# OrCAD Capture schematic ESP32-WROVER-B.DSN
size C; title: ESP32-WROVER-B; rev: 1.0
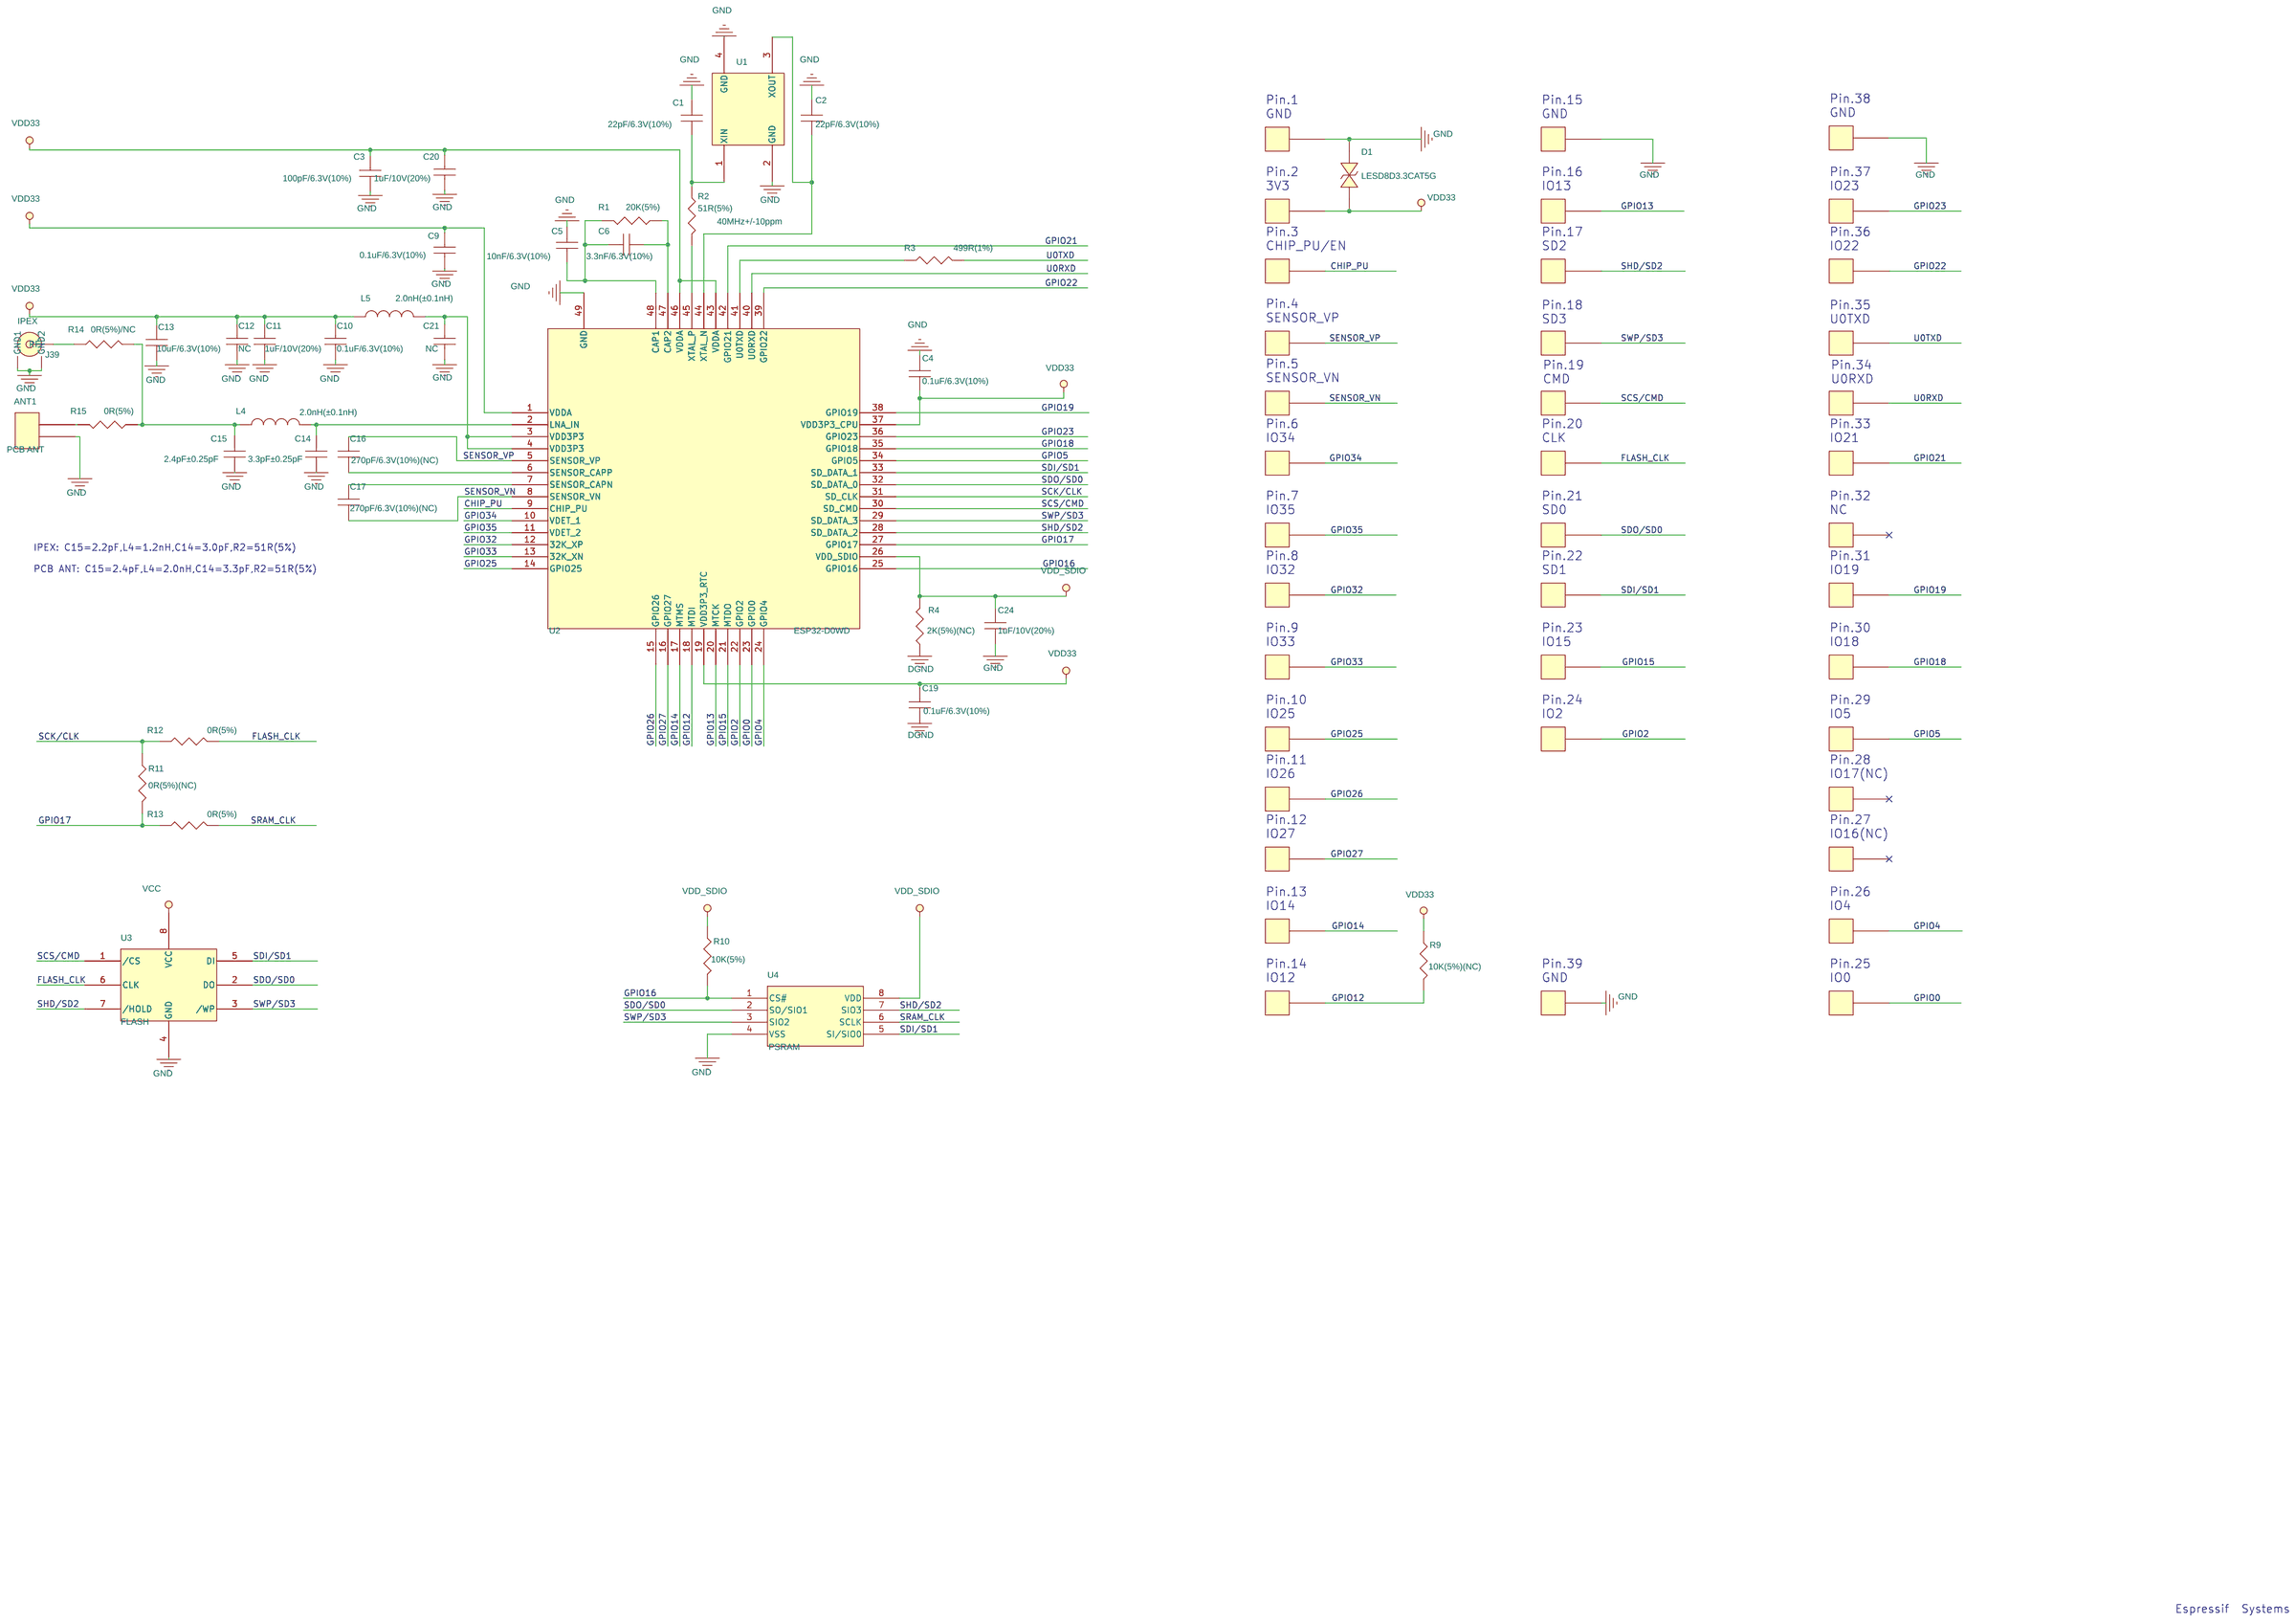
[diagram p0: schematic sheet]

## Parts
ANT1  PCB ANT  [MINI_ANT_TYPEA]
C1  22pF/6.3V(10%)  [C0201]
C2  22pF/6.3V(10%)  [C0201]
C3  100pF/6.3V(10%)  [C0201]
C4  0.1uF/6.3V(10%)  [C0201]
C5  10nF/6.3V(10%)  [C0201]
C6  3.3nF/6.3V(10%)  [C0201]
C9  0.1uF/6.3V(10%)  [C0201]
C10  0.1uF/6.3V(10%)  [C0201]
C11  1uF/10V(20%)  [C0201]
C12  NC  [C0402]
C13  10uF/6.3V(10%)  [C0402]
C14  3.3pF±0.25pF  [C0201]
C15  2.4pF±0.25pF  [C0201]
C16  270pF/6.3V(10%)(NC)  [C0201]
C17  270pF/6.3V(10%)(NC)  [C0201]
C19  0.1uF/6.3V(10%)  [C0201]
C20  1uF/10V(20%)  [C0201]
C21  NC  [C0201]
C24  1uF/10V(20%)  [C0201]
D1  LESD8D3.3CAT5G  [SOD882]
EP  CON1  [SPAD_1]
J1  CON1  [SPAD_1]
J2  CON1  [SPAD_1]
J3  CON1  [SPAD_1]
J4  CON1  [SPAD_1]
J5  CON1  [SPAD_1]
J6  CON1  [SPAD_1]
J7  CON1  [SPAD_1]
J8  CON1  [SPAD_1]
J9  CON1  [SPAD_1]
J10  CON1  [SPAD_1]
J11  CON1  [SPAD_1]
J12  CON1  [SPAD_1]
J13  CON1  [SPAD_1]
J14  CON1  [SPAD_1]
J15  CON1  [SPAD_1]
J16  CON1  [SPAD_1]
J17  CON1  [SPAD_1]
J18  CON1  [SPAD_1]
J19  CON1  [SPAD_1]
J20  CON1  [SPAD_1]
J21  CON1  [SPAD_1]
J22  CON1  [SPAD_1]
J23  CON1  [SPAD_1]
J24  CON1  [SPAD_1]
J25  CON1  [SPAD_1]
J26  CON1  [SPAD_1]
J27  CON1  [SPAD_1]
J28  CON1  [SPAD_1]
J29  CON1  [SPAD_1]
J30  CON1  [SPAD_1]
J31  CON1  [SPAD_1]
J32  CON1  [SPAD_1]
J33  CON1  [SPAD_1]
J34  CON1  [SPAD_1]
J35  CON1  [SPAD_1]
J36  CON1  [SPAD_1]
J37  CON1  [SPAD_1]
J38  CON1  [SPAD_1]
J39  IPEX  [ECT818000368]
L4  2.0nH(±0.1nH)  [L0201]
L5  2.0nH(±0.1nH)  [L0201]
R1  20K(5%)  [R0201]
R2  51R(5%)  [R0201]
R3  499R(1%)  [R0201]
R4  2K(5%)(NC)  [R0201]
R9  10K(5%)(NC)  [R0201]
R10  10K(5%)  [R0201]
R11  0R(5%)(NC)  [R0201]
R12  0R(5%)  [R0201]
R13  0R(5%)  [R0201]
R14  0R(5%)/NC  [R0201A]
R15  0R(5%)  [R0201A]
U1  40MHz+/-10ppm  [3225]
U2  ESP32-D0WD  [SLP48_5X5]
U3  FLASH  [SOIC08-WN]
U4  PSRAM  [SOIC-8P]

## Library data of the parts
ANT1 = CON2
C1-C6 C9-C17 C19-C21 C24 = CAP_NP
D1 = DIODE_BI-DIR_TRIG: Options: ESD
EP J1-J38 = CON1
J39 = IPEX_0
L4 L5 = CHOKE
R1-R4 R9-R15 = RESISTOR
U1 = X1_1
U2 = ESP8080_24
U3 = FLASH_3
U4 = PN18S32

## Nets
GND: ANT1.2 C1.2 C2.2 C3.2 C4.2 C5.2 C9.2 C10.2 C11.2 C12.2 C13.2 C14.1 C15.1 C19.2 C20.2 C21.2 C24.2 D1.2 EP.1 J1.1 J5.1 J28.1 J39.2(GND1) J39.3(GND2) R4.2 U1.2(GND) U1.4(GND) U2.49(GND) U3.4(GND) U4.4(VSS)
VDD33: C3.1 C4.1 C9.1 C10.1 C11.1 C12.1 C13.1 C19.1 C20.1 D1.1 J3.1 L5.2 R9.1 U2.1(VDDA) U2.19(VDD3P3_RTC) U2.37(VDD3P3_CPU) U2.43(VDDA) U2.46(VDDA)
VDD_SDIO: C24.1 R4.1 R10.1 U2.26(VDD_SDIO) U3.8(VCC) U4.8(VDD)
CHIP_PU: J6.1 U2.9(CHIP_PU)
FLASH_CLK: J19.1 R12.2 U3.6(CLK)
GPIO0: J34.1 U2.23(GPIO0)
GPIO2: J36.1 U2.22(GPIO2)
GPIO4: J32.1 U2.24(GPIO4)
GPIO5: J24.1 U2.34(GPIO5)
GPIO12: J35.1 R9.2 U2.18(MTDI)
GPIO13: J37.1 U2.20(MTCK)
GPIO14: J33.1 U2.17(MTMS)
GPIO15: J38.1 U2.21(MTDO)
GPIO16: R10.2 U2.25(GPIO16) U4.1(CS#)
GPIO17: R11.2 R13.1 U2.27(GPIO17)
GPIO18: J21.1 U2.35(GPIO18)
GPIO19: J18.1 U2.38(GPIO19)
GPIO21: J12.1 U2.42(GPIO21)
GPIO22: J4.1 U2.39(GPIO22)
GPIO23: J2.1 U2.36(GPIO23)
GPIO25: J26.1 U2.14(GPIO25)
GPIO26: J29.1 U2.15(GPIO26)
GPIO27: J31.1 U2.16(GPIO27)
GPIO32: J20.1 U2.12(32K_XP)
GPIO33: J23.1 U2.13(32K_XN)
GPIO34: J14.1 U2.10(VDET_1)
GPIO35: J17.1 U2.11(VDET_2)
SCK/CLK: R11.1 R12.1 U2.31(SD_CLK)
SCS/CMD: J16.1 U2.30(SD_CMD) U3.1(/CS)
SDI/SD1: J25.1 U2.33(SD_DATA_1) U3.5(DI) U4.5(SI/SIO0)
SDO/SD0: J22.1 U2.32(SD_DATA_0) U3.2(DO) U4.2(SO/SIO1)
SENSOR_VN: C17.2 J11.1 U2.8(SENSOR_VN)
SENSOR_VP: C16.1 J8.1 U2.5(SENSOR_VP)
SHD/SD2: J10.1 U2.28(SD_DATA_2) U3.7(/HOLD) U4.7(SIO3)
SRAM_CLK: R13.2 U4.6(SCLK)
SWP/SD3: J13.1 U2.29(SD_DATA_3) U3.3(/WP) U4.3(SIO2)
U0RXD: J9.1 U2.40(U0RXD)
U0TXD: J7.1 R3.2
N16680112: C21.1 L5.1 U2.3(VDD3P3) U2.4(VDD3P3)
N16680176: C5.1 C6.2 R1.2 U2.48(CAP1)
N16680200: C15.2 L4.2 R14.2 R15.1
N16680240: ANT1.1 R15.2
N16680244: C2.1 U1.3(XOUT) U2.44(XTAL_N)
N16680316: C1.1 R2.1 U1.1(XIN)
N16680402: C16.2 U2.6(SENSOR_CAPP)
N16680410: C17.1 U2.7(SENSOR_CAPN)
N16680498: C6.1 R1.1 U2.47(CAP2)
N16681146: R3.1 U2.41(U0TXD)
N16687029: C14.2 L4.1 U2.2(LNA_IN)
N16707690: R2.2 U2.45(XTAL_P)
N16710353: J39.1(RF) R14.1

Not connected (* = marked no-connect by the designer): J15 1*; J27 1*; J30 1*

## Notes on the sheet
- Pin.38
  GND
- Pin.1
  GND
- Pin.15
  GND
- Pin.2
  3V3
- Pin.16
  IO13
- Pin.37
  IO23
- Pin.3
  CHIP_PU/EN
- Pin.17
  SD2
- Pin.36
  IO22
- Pin.4
  SENSOR_VP
- Pin.18
  SD3
- Pin.35
  U0TXD
- Pin.5
  SENSOR_VN
- Pin.19
  CMD
- Pin.34
  U0RXD
- Pin.6
  IO34
- Pin.20
  CLK
- Pin.33
  IO21
- Pin.7
  IO35
- Pin.21
  SD0
- Pin.32
  NC
- IPEX: C15=2.2pF,L4=1.2nH,C14=3.0pF,R2=51R(5%)
  PCB ANT: C15=2.4pF,L4=2.0nH,C14=3.3pF,R2=51R(5%)
- Pin.8
  IO32
- Pin.22
  SD1
- Pin.31
  IO19
- Pin.9
  IO33
- Pin.23
  IO15
- Pin.30
  IO18
- Pin.10
  IO25
- Pin.24
  IO2
- Pin.29
  IO5
- Pin.11
  IO26
- Pin.28
  IO17(NC)
- Pin.12
  IO27
- Pin.27
  IO16(NC)
- Pin.13
  IO14
- Pin.26
  IO4
- Pin.14
  IO12
- Pin.39
  GND
- Pin.25
  IO0
- Espressif  Systems
